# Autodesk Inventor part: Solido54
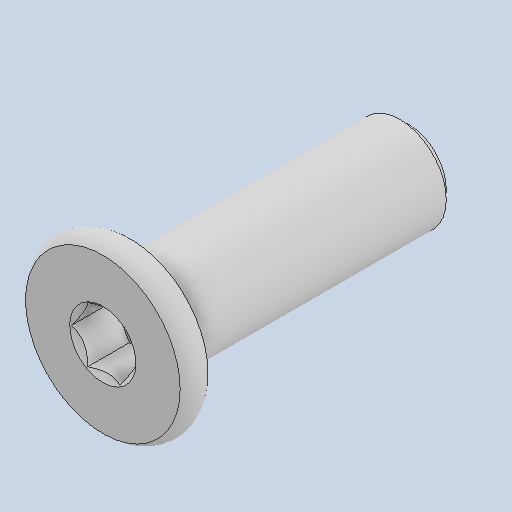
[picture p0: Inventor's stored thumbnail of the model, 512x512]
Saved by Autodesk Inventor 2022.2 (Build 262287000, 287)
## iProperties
Created: 2024-10
Part Number: Solido54
Material: Generico
Document SubType Name: Modeling
Designer: 18907419
Density: 1 g/cm^3
Appearance: Default
Author: 18907419
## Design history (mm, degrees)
feature "Solido54"
node "Solido1"
